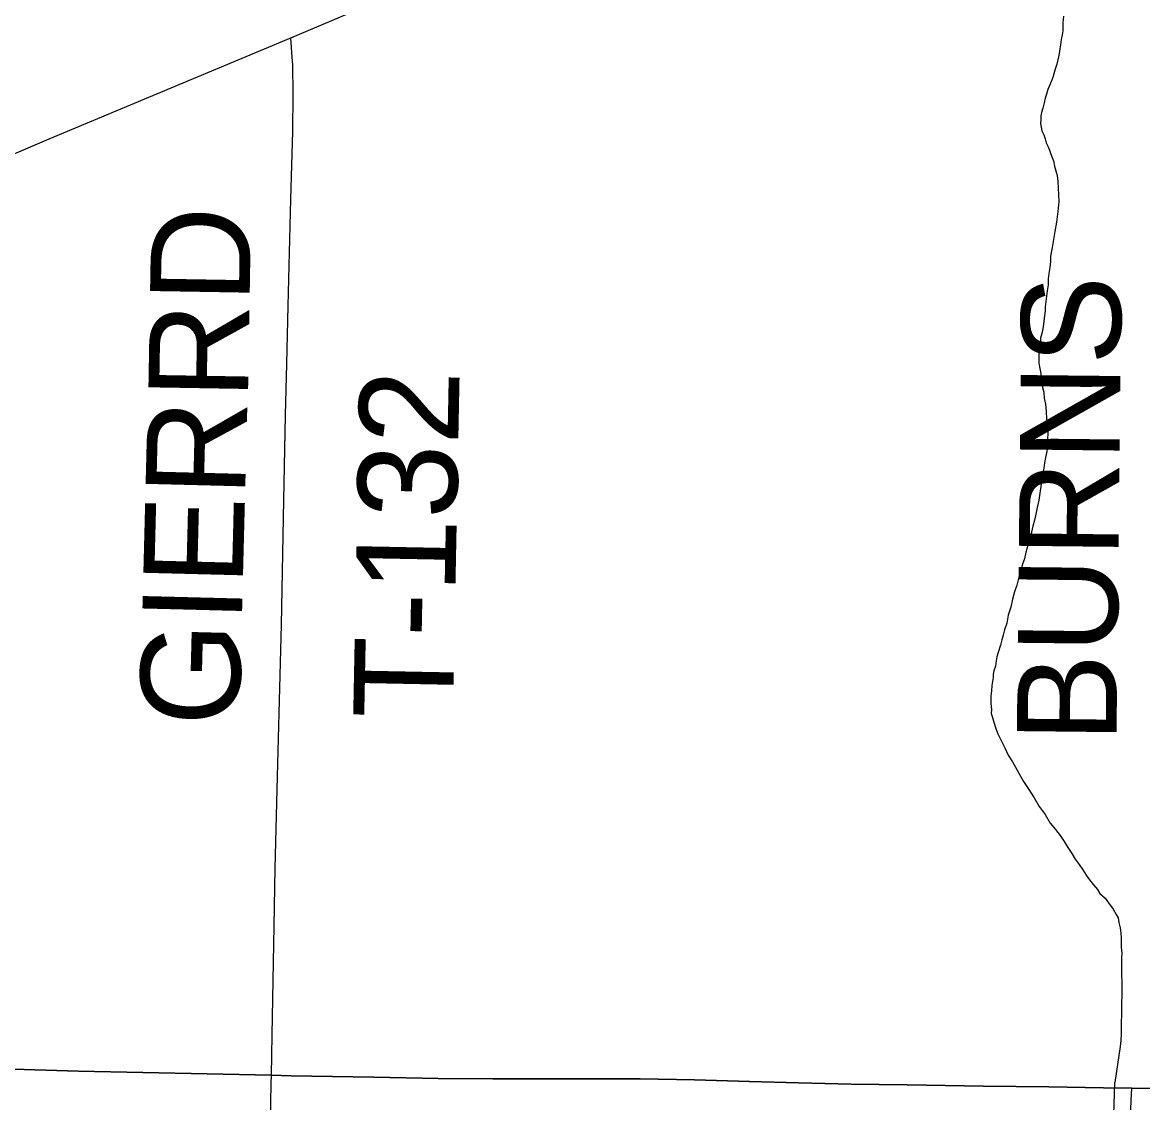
# Model space of a CAD drawing. Extents: x 0 to 64.8, y -5 to 22.
# Drawn here: x 7.614 to 8.252, y 19.777 to 20.393 of the extents above; entities that cross this region are included whole.
import ezdxf

# ---------------------------------------------------------------- set-up
doc = ezdxf.new("R2010")
doc.units = 0
for name, color, linetype in [('GM_X_Adjacent_County', 7, 'Continuous'), ('GM_X_County', 7, 'Continuous'), ('GM_X_County_Road', 7, 'Continuous'), ('GM_X_Minor_River', 7, 'Continuous'), ('GM_X_Township', 7, 'Continuous'), ('GM_X_Township_Road', 7, 'Continuous'), ('GM_X_Township_Road_Text', 7, 'Continuous')]:
    doc.layers.add(name, color=color, linetype=linetype)

msp = doc.modelspace()

# ---------------------------------------------------------------- linework, layer by layer
at = {"layer": 'GM_X_Adjacent_County'}
for points in [[(7.55859, 19.79776), (7.64563, 19.79517), (7.75555, 19.79277), (7.76678, 19.79252), (7.81392, 19.79166), (7.85065, 19.79099), (7.88172, 19.79075), (7.9159, 19.79068), (7.96561, 19.79068), (7.99668, 19.79009), (8.02808, 19.78926), (8.05588, 19.78843), (8.08592, 19.7877), (8.11781, 19.78723), (8.1613, 19.78658), (8.19859, 19.78611), (8.22984, 19.78567), (8.24581, 19.78544), (8.25825, 19.78527)], [(8.25825, 19.78527), (8.24581, 19.78544), (8.22984, 19.78567), (8.19859, 19.78611), (8.1613, 19.78658), (8.11781, 19.78723), (8.08592, 19.7877), (8.05588, 19.78843), (8.02808, 19.78926), (7.99668, 19.79009), (7.96561, 19.79068), (7.9159, 19.79068), (7.88172, 19.79075), (7.85065, 19.79099), (7.81392, 19.79166), (7.76678, 19.79252), (7.75555, 19.79277), (7.64563, 19.79517), (7.55859, 19.79776)]]:
    msp.add_lwpolyline(points, dxfattribs=at)
at = {"layer": 'GM_X_County'}
for points in [[(8.25825, 19.78527), (8.24581, 19.78544), (8.22984, 19.78567), (8.19859, 19.78611), (8.1613, 19.78658), (8.11781, 19.78723), (8.08592, 19.7877), (8.05588, 19.78843), (8.02808, 19.78926), (7.99668, 19.79009), (7.96561, 19.79068), (7.9159, 19.79068), (7.88172, 19.79075), (7.85065, 19.79099), (7.81392, 19.79166), (7.76678, 19.79252), (7.75555, 19.79277), (7.64563, 19.79517), (7.55859, 19.79776)], [(7.55859, 19.79776), (7.64563, 19.79517), (7.75555, 19.79277), (7.76678, 19.79252), (7.81392, 19.79166), (7.85065, 19.79099), (7.88172, 19.79075), (7.9159, 19.79068), (7.96561, 19.79068), (7.99668, 19.79009), (8.02808, 19.78926), (8.05588, 19.78843), (8.08592, 19.7877), (8.11781, 19.78723), (8.1613, 19.78658), (8.19859, 19.78611), (8.22984, 19.78567), (8.24581, 19.78544), (8.25825, 19.78527)]]:
    msp.add_lwpolyline(points, dxfattribs=at)
at = {"layer": 'GM_X_County_Road'}
for points in [[(7.76671, 20.38376), (7.79978, 20.39779), (7.8472, 20.41815), (7.86494, 20.42566), (7.94881, 20.46196), (8.01634, 20.49066), (8.07178, 20.51438), (8.09234, 20.52321), (8.11806, 20.53422), (8.15868, 20.55151), (8.19071, 20.56513), (8.24997, 20.591), (8.26832, 20.59909)], [(6.75284, 19.95766), (6.80726, 19.98025), (6.85244, 19.99948), (6.87417, 20.00875), (6.91252, 20.02503), (6.96007, 20.04507), (7.02717, 20.07314), (7.077, 20.09418), (7.09765, 20.10284), (7.11602, 20.11045), (7.14006, 20.12064), (7.18592, 20.13989), (7.21406, 20.15158), (7.25305, 20.16789), (7.29026, 20.18365), (7.36081, 20.21315), (7.3815, 20.22168), (7.42837, 20.24172), (7.49656, 20.27044), (7.56137, 20.29757), (7.5906, 20.30984), (7.62895, 20.32611), (7.74942, 20.37642), (7.76671, 20.38376)], [(7.73352, 18.76581), (7.73358, 18.78075), (7.73431, 18.82427), (7.73654, 18.92998), (7.73889, 19.0388), (7.73973, 19.08234), (7.74201, 19.18805), (7.74379, 19.24399), (7.74514, 19.29996), (7.7467, 19.34969), (7.74804, 19.39633), (7.75013, 19.47717), (7.75062, 19.52382), (7.75129, 19.57667), (7.75249, 19.62953), (7.75426, 19.71348), (7.75495, 19.76635), (7.75544, 19.78809), (7.75555, 19.79277)]]:
    msp.add_lwpolyline(points, dxfattribs=at)
at = {"layer": 'GM_X_Minor_River'}
for points in [[(8.20704, 20.396), (8.2066, 20.3922), (8.20657, 20.38992), (8.20653, 20.38765), (8.20611, 20.38537), (8.20569, 20.38272), (8.20526, 20.37969), (8.20485, 20.37741), (8.20443, 20.37476), (8.20402, 20.37286), (8.20319, 20.3687), (8.202, 20.3653)], [(8.202, 20.3653), (8.20079, 20.36114), (8.1992, 20.35698), (8.19802, 20.35434), (8.19722, 20.35169), (8.19642, 20.34942), (8.196, 20.34677), (8.19519, 20.34374), (8.19439, 20.3411), (8.19398, 20.3392), (8.19395, 20.3373), (8.19391, 20.33502), (8.19461, 20.33083), (8.19571, 20.32853), (8.19644, 20.32624), (8.19716, 20.32395), (8.19827, 20.32165), (8.199, 20.31974), (8.19972, 20.31745), (8.20045, 20.31554), (8.20118, 20.31363), (8.2019, 20.31058), (8.20261, 20.3079), (8.20333, 20.30523), (8.20366, 20.30181), (8.20424, 20.2904), (8.20377, 20.28471), (8.20292, 20.27864), (8.20207, 20.27333), (8.20124, 20.26878), (8.20041, 20.26424), (8.19957, 20.25931), (8.19952, 20.25627), (8.19909, 20.25286), (8.19865, 20.24945), (8.19823, 20.24641), (8.19817, 20.24299), (8.19774, 20.23958), (8.19731, 20.23655), (8.19688, 20.23351), (8.19646, 20.23048), (8.19642, 20.2282), (8.19597, 20.22403), (8.19554, 20.22061), (8.19512, 20.21796), (8.19469, 20.21531), (8.19389, 20.21266), (8.19386, 20.21038), (8.19344, 20.20773), (8.19302, 20.20583), (8.19299, 20.20355), (8.19294, 20.20052), (8.19291, 20.19861), (8.19326, 20.19633), (8.19361, 20.19442), (8.19396, 20.19252), (8.19429, 20.18985), (8.19464, 20.18719), (8.19497, 20.18452), (8.19569, 20.18185), (8.19602, 20.17843), (8.19672, 20.17499), (8.19704, 20.17081), (8.19735, 20.16662), (8.19804, 20.16205), (8.19799, 20.15863), (8.19793, 20.15484), (8.19787, 20.15103), (8.19744, 20.148), (8.19663, 20.14459), (8.1962, 20.14156), (8.19577, 20.13853), (8.19496, 20.1355), (8.19453, 20.13209), (8.19282, 20.12033), (8.192, 20.11616), (8.19118, 20.11238), (8.19036, 20.10897), (8.18955, 20.10557), (8.18874, 20.10216), (8.18792, 20.09837), (8.18671, 20.09459), (8.18551, 20.09081), (8.18469, 20.08702), (8.1835, 20.084), (8.18269, 20.08021), (8.18148, 20.07643), (8.18027, 20.07189), (8.17907, 20.06811), (8.17786, 20.06395), (8.17703, 20.0594), (8.17544, 20.05487), (8.17461, 20.05032), (8.17341, 20.04654), (8.1726, 20.04351), (8.1718, 20.04086), (8.17099, 20.03784), (8.16978, 20.03368), (8.16898, 20.03103), (8.16856, 20.02875), (8.16814, 20.02572)], [(8.16814, 20.02572), (8.16733, 20.02307), (8.16692, 20.02118), (8.16689, 20.01928), (8.16648, 20.01701), (8.16606, 20.01473), (8.16601, 20.0117), (8.16559, 20.00866), (8.16556, 20.00676), (8.16552, 20.00448), (8.16585, 20.00106), (8.16581, 19.99878), (8.16654, 19.99648), (8.16725, 19.99381), (8.16834, 19.99038), (8.16944, 19.98732), (8.17165, 19.9831), (8.17349, 19.97927), (8.17533, 19.97507), (8.17793, 19.97122), (8.18422, 19.9601), (8.18719, 19.9555), (8.19016, 19.95089), (8.19313, 19.9459), (8.19648, 19.94129), (8.19945, 19.9363), (8.20243, 19.93284), (8.20504, 19.92937), (8.20727, 19.92592), (8.2095, 19.92246), (8.21172, 19.91901), (8.21358, 19.91594), (8.21581, 19.91286), (8.21805, 19.90979), (8.2199, 19.90672), (8.22176, 19.90403), (8.224, 19.90133), (8.22624, 19.89863), (8.22772, 19.89633), (8.23073, 19.89363), (8.23259, 19.89094), (8.23519, 19.88747), (8.23705, 19.88441), (8.23816, 19.88249), (8.2385, 19.87982), (8.23921, 19.87677), (8.23954, 19.87372), (8.23988, 19.87106), (8.23984, 19.8684), (8.2398, 19.86574), (8.24012, 19.86232), (8.24008, 19.85966), (8.24002, 19.85548), (8.23994, 19.85054), (8.24024, 19.84521), (8.24018, 19.84141), (8.24011, 19.83723), (8.24007, 19.83495), (8.24004, 19.83267), (8.24, 19.83002), (8.23995, 19.82698), (8.23989, 19.82318), (8.23984, 19.81976), (8.23978, 19.81634), (8.23972, 19.81254), (8.23929, 19.80913), (8.23616, 19.78868)], [(8.23015, 19.59296), (8.23616, 19.78867)]]:
    msp.add_lwpolyline(points, dxfattribs=at)
at = {"layer": 'GM_X_Township'}
for points in [[(8.25825, 19.78527), (8.24581, 19.78544), (8.22984, 19.78567), (8.19859, 19.78611), (8.1613, 19.78658), (8.11781, 19.78723), (8.08592, 19.7877), (8.05588, 19.78843), (8.02808, 19.78926), (7.99668, 19.79009), (7.96561, 19.79068), (7.9159, 19.79068), (7.88172, 19.79075), (7.85065, 19.79099), (7.81392, 19.79166), (7.76678, 19.79252), (7.75555, 19.79277), (7.64563, 19.79517), (7.55859, 19.79776)], [(7.55859, 19.79776), (7.64563, 19.79517), (7.75555, 19.79277), (7.76678, 19.79252), (7.81392, 19.79166), (7.85065, 19.79099), (7.88172, 19.79075), (7.9159, 19.79068), (7.96561, 19.79068), (7.99668, 19.79009), (8.02808, 19.78926), (8.05588, 19.78843), (8.08592, 19.7877), (8.11781, 19.78723), (8.1613, 19.78658), (8.19859, 19.78611), (8.22984, 19.78567), (8.24581, 19.78544), (8.25825, 19.78527)]]:
    msp.add_lwpolyline(points, dxfattribs=at)
at = {"layer": 'GM_X_Township_Road'}
for points in [[(7.75555, 19.79277), (7.75593, 19.81563), (7.75709, 19.87781), (7.75773, 19.91076), (7.75898, 19.96299), (7.76004, 19.99905), (7.76126, 20.04941), (7.76255, 20.12029), (7.76359, 20.16879), (7.76428, 20.19802), (7.76503, 20.23097), (7.76662, 20.29189), (7.76775, 20.33044), (7.76796, 20.35158), (7.76775, 20.36837), (7.76746, 20.37271), (7.76671, 20.38376)], [(7.55859, 19.79776), (7.64562, 19.79517), (7.75555, 19.79277)], [(7.55859, 19.79776), (7.64562, 19.79517), (7.75555, 19.79277)], [(7.75555, 19.79277), (7.76678, 19.79252), (7.81392, 19.79166), (7.85065, 19.79099), (7.88171, 19.79075), (7.91589, 19.79068), (7.96561, 19.79068), (7.99668, 19.79009), (8.02808, 19.78926), (8.05588, 19.78843), (8.08592, 19.7877), (8.11781, 19.78723), (8.1613, 19.78658), (8.19859, 19.78612), (8.22984, 19.78567), (8.24581, 19.78544)], [(7.75555, 19.79277), (7.76678, 19.79252), (7.81392, 19.79166), (7.85065, 19.79099), (7.88171, 19.79075), (7.91589, 19.79068), (7.96561, 19.79068), (7.99668, 19.79009), (8.02808, 19.78926), (8.05588, 19.78843), (8.08592, 19.7877), (8.11781, 19.78723), (8.1613, 19.78658), (8.19859, 19.78612), (8.22984, 19.78567), (8.24581, 19.78544)], [(8.23753, 19.43634), (8.2394, 19.52369), (8.24308, 19.6914), (8.24487, 19.76283), (8.24551, 19.77834), (8.24581, 19.78544)], [(8.24581, 19.78544), (8.25825, 19.78527)], [(8.24581, 19.78544), (8.25825, 19.78527)]]:
    msp.add_lwpolyline(points, dxfattribs=at)

# ---------------------------------------------------------------- texts
at = {"layer": 'GM_X_Township_Road_Text'}
for s, rotation, p in [('RD', 89.02801, (7.74217, 20.17746)), ('BURNS', 89.38209, (8.23713, 19.98198)), ('T-132', 88.87648, (7.85895, 19.99552)), ('GIER', 88.53923, (7.73717, 19.99114))]:
    msp.add_text(s, height=0.056818, rotation=rotation, dxfattribs=at).set_placement(p)

doc.saveas('drawing.dxf')
